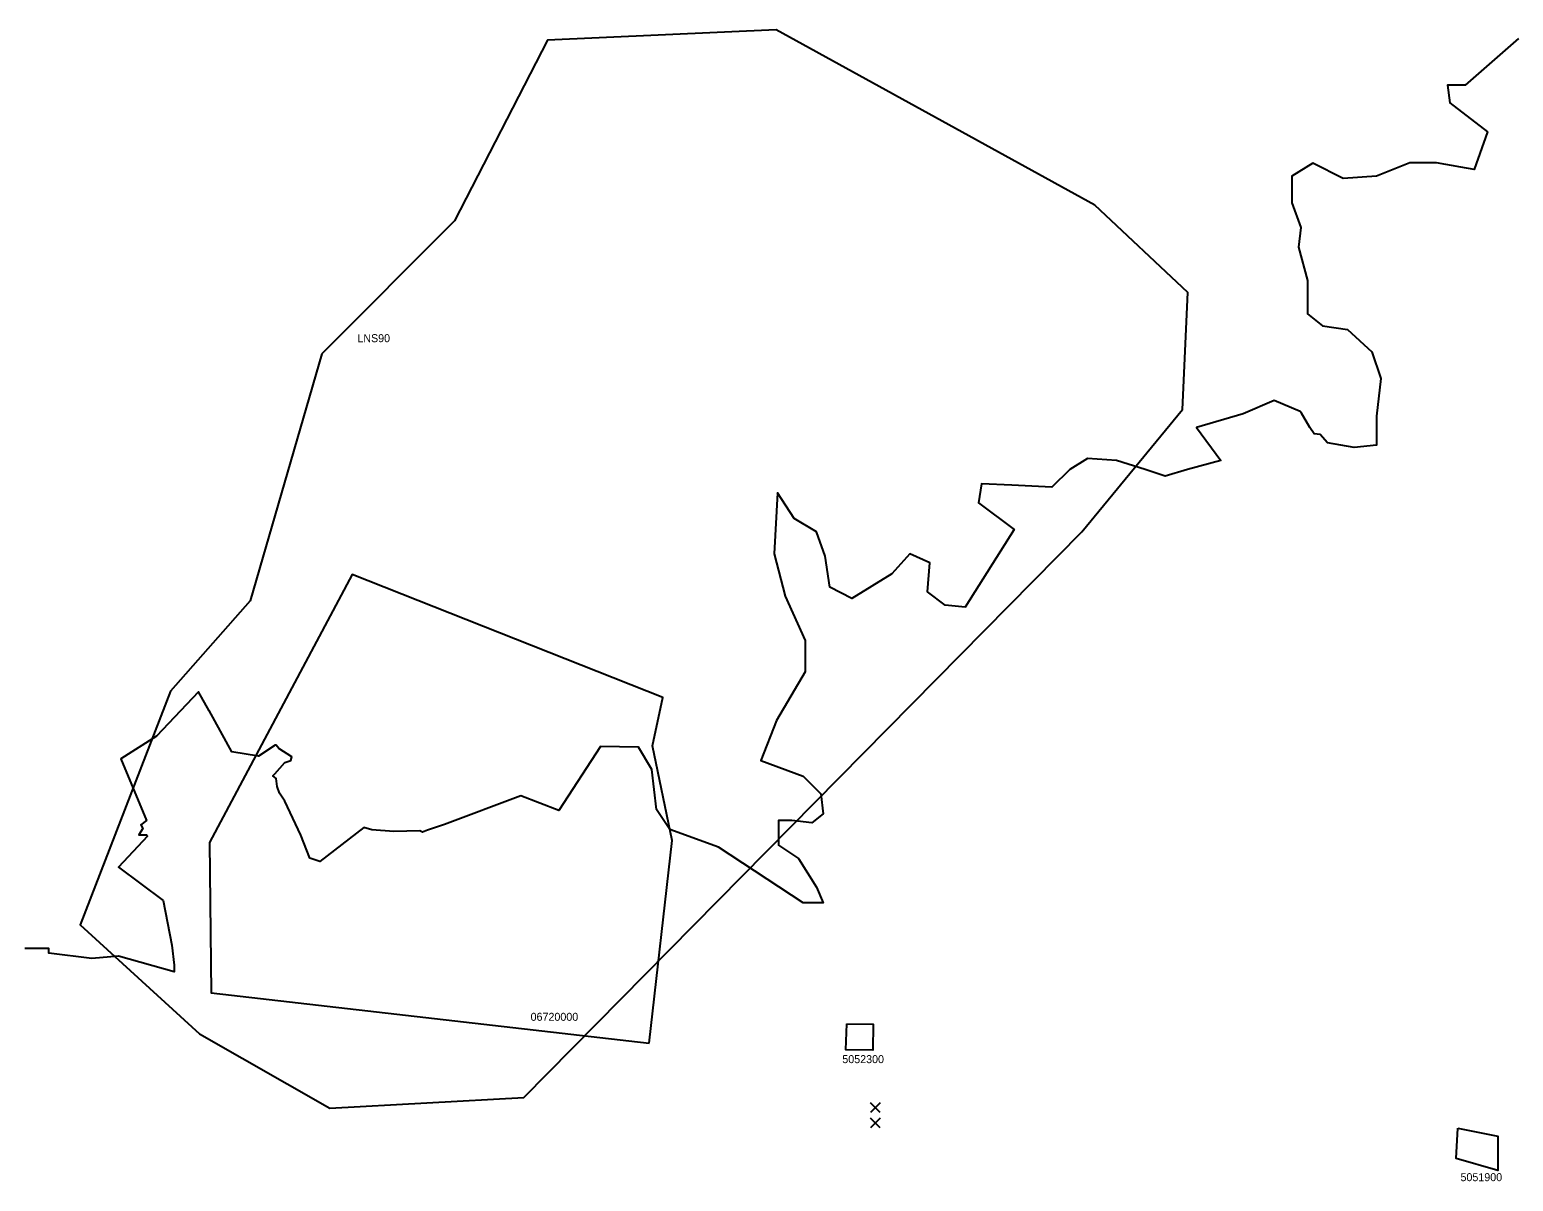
# Model space of a CAD drawing. Extents: x -556199 to -540209, y -1046851 to -1035695.
# Drawn here: x -544149 to -542295, y -1043116 to -1041676 of the extents above; entities that cross this region are included whole.
import ezdxf

# ---------------------------------------------------------------- set-up
doc = ezdxf.new("R2010")
doc.units = 0
for name, color, linetype in [('ft_08_KOMS_rr_trasa_l_RRT_STAV', 7, 'Continuous'), ('Vrstva 24', 7, 'Continuous'), ('Vrstva 40', 7, 'Continuous'), ('Vrstva 47', 7, 'Continuous'), ('Vrstva 48', 7, 'Continuous')]:
    doc.layers.add(name, color=color, linetype=linetype)

msp = doc.modelspace()

# ---------------------------------------------------------------- linework, layer by layer
at = {"layer": 'ft_08_KOMS_rr_trasa_l_RRT_STAV'}
for p, q in [((-543085.9, -1043017.7), (-543097.9, -1043029.7)), ((-543085.9, -1043029.7), (-543097.9, -1043017.7)), ((-543085.9, -1043036.8), (-543097.9, -1043048.8)), ((-543085.9, -1043048.8), (-543097.9, -1043036.8))]:
    msp.add_line(p, q, dxfattribs=at)
at = {"layer": 'Vrstva 24'}
msp.add_lwpolyline([(-542288.3, -1041687.4), (-542354.9, -1041745.7), (-542377.1, -1041745.7), (-542374.4, -1041768), (-542327.2, -1041804.1), (-542343.8, -1041851.3), (-542360.5, -1041848.5), (-542391, -1041842.9), (-542424.3, -1041842.9), (-542466, -1041859.6), (-542507.7, -1041862.4), (-542545.4, -1041843.5), (-542571.5, -1041859.6), (-542571.5, -1041892.9), (-542560.4, -1041923.5), (-542563.2, -1041948.4), (-542552.1, -1041990.1), (-542552.1, -1042031.7), (-542533.4, -1042046.7), (-542502.1, -1042051.2), (-542471.6, -1042079), (-542460.4, -1042112.3), (-542466, -1042159.5), (-542466, -1042195.6), (-542493.8, -1042198.4), (-542527.1, -1042192.8), (-542536.3, -1042182.2), (-542543.8, -1042181.7), (-542549.3, -1042173.4), (-542559.5, -1042155.5), (-542561.2, -1042153.6), (-542593.7, -1042140), (-542632.6, -1042156.7), (-542690.9, -1042173.4), (-542660.4, -1042215), (-542702, -1042226.1), (-542729.8, -1042234.5), (-542754.8, -1042226.1), (-542790.9, -1042215), (-542827, -1042212.2), (-542849.2, -1042226.1), (-542871.4, -1042248.3), (-542921.4, -1042245.6), (-542959.3, -1042244.2), (-542963, -1042267.8), (-542918.6, -1042301.1), (-542979.7, -1042398.3), (-543004.7, -1042395.5), (-543026.9, -1042378.8), (-543024.1, -1042342.7), (-543049.1, -1042331.6), (-543071.3, -1042356.6), (-543121.3, -1042387.2), (-543149.1, -1042373.3), (-543154.6, -1042334.4), (-543165.7, -1042303.9), (-543193.5, -1042287.2), (-543214.4, -1042255.1), (-543218.5, -1042331.6), (-543204.6, -1042384.4), (-543179.6, -1042439.9), (-543179.6, -1042478.8), (-543215.7, -1042539.9), (-543235.2, -1042589.9), (-543182.4, -1042609.3), (-543160.2, -1042631.5), (-543157.4, -1042656.5), (-543171.3, -1042667.6), (-543196.3, -1042664.9), (-543212.9, -1042664.9), (-543212.9, -1042695.4), (-543188, -1042712.1), (-543165.7, -1042748.2), (-543157.4, -1042767.6), (-543182.4, -1042767.6), (-543287.9, -1042698.2), (-543349, -1042676), (-543365.7, -1042651), (-543371.2, -1042601), (-543387.9, -1042573.2), (-543435.6, -1042572.1), (-543487.5, -1042652), (-543535.1, -1042633.8), (-543630.2, -1042669.8), (-543651.7, -1042676.8), (-543657.8, -1042679.2), (-543661.2, -1042677.6), (-543693.9, -1042678.5), (-543721, -1042676.5), (-543731, -1042673.5), (-543786.3, -1042715.8), (-543798.6, -1042711.7), (-543809.7, -1042683.2), (-543829.9, -1042640.7), (-543836.4, -1042630.5), (-543839.4, -1042622.1), (-543840.9, -1042612.4), (-543845, -1042608.9), (-543842.4, -1042606.5), (-543830, -1042592.1), (-543822.2, -1042589.6), (-543821, -1042585.3), (-543837.4, -1042574.7), (-543840.8, -1042570.5), (-543842.1, -1042570.6), (-543862.7, -1042584.3), (-543896, -1042578.8), (-543924.6, -1042527.2), (-543924.6, -1042527.5), (-543937.7, -1042503.8), (-543990.4, -1042559.3), (-544034.7, -1042587.5), (-544002.6, -1042664.8), (-544009.8, -1042670), (-544007.2, -1042674.6), (-544012.5, -1042682.5), (-544002.6, -1042682.5), (-544001.5, -1042684.3), (-544037.6, -1042723.2), (-543982.1, -1042764.8), (-543971, -1042820.3), (-543968.2, -1042845.3), (-543968.2, -1042853.7), (-544037.6, -1042834.2), (-544071, -1042837), (-544124.6, -1042830.3), (-544124.6, -1042824.5), (-544154.9, -1042824.5)], dxfattribs=at)
at = {"layer": 'Vrstva 40'}
msp.add_lwpolyline([(-543374.5, -1042943), (-543345.9, -1042689.8), (-543370.5, -1042571.2), (-543357.6, -1042511.1), (-543745.6, -1042357.1), (-543924, -1042692), (-543922.1, -1042880.2), (-543374.5, -1042943)], dxfattribs=at)
at = {"layer": 'Vrstva 47'}
for points in [[(-543127.6, -1042918.8), (-543094.7, -1042919.4), (-543095.2, -1042951.8), (-543128.8, -1042951.2)], [(-542364.1, -1043049.3), (-542314.3, -1043059.2), (-542314.3, -1043102), (-542366.4, -1043086.9)]]:
    msp.add_lwpolyline(points, close=True, dxfattribs=at)
at = {"layer": 'Vrstva 48'}
msp.add_lwpolyline([(-543783.7, -1042081.5), (-543873.3, -1042390.2), (-543972.9, -1042503.1), (-544085.8, -1042795.2), (-543936.4, -1042931.3), (-543773.7, -1043024.3), (-543531.4, -1043011), (-542834.2, -1042303.9), (-542708.1, -1042151.2), (-542701.4, -1042005.1), (-542817.6, -1041895.6), (-543216, -1041676.5), (-543501.5, -1041689.8), (-543617.7, -1041915.5), (-543783.7, -1042081.5)], dxfattribs=at)

# ---------------------------------------------------------------- texts
at = {"layer": 'Vrstva 40'}
msp.add_text('06720000', height=10, dxfattribs=at).set_placement((-543522.8, -1042915))
at = {"layer": 'Vrstva 47'}
for s, p in [('5052300', (-543133.3, -1042967.9)), ('5051900', (-542360.9, -1043115.4))]:
    msp.add_text(s, height=10, dxfattribs=at).set_placement(p)
at = {"layer": 'Vrstva 48'}
msp.add_text('LNS90', height=10, dxfattribs=at).set_placement((-543739.3, -1042067))

doc.saveas('drawing.dxf')
